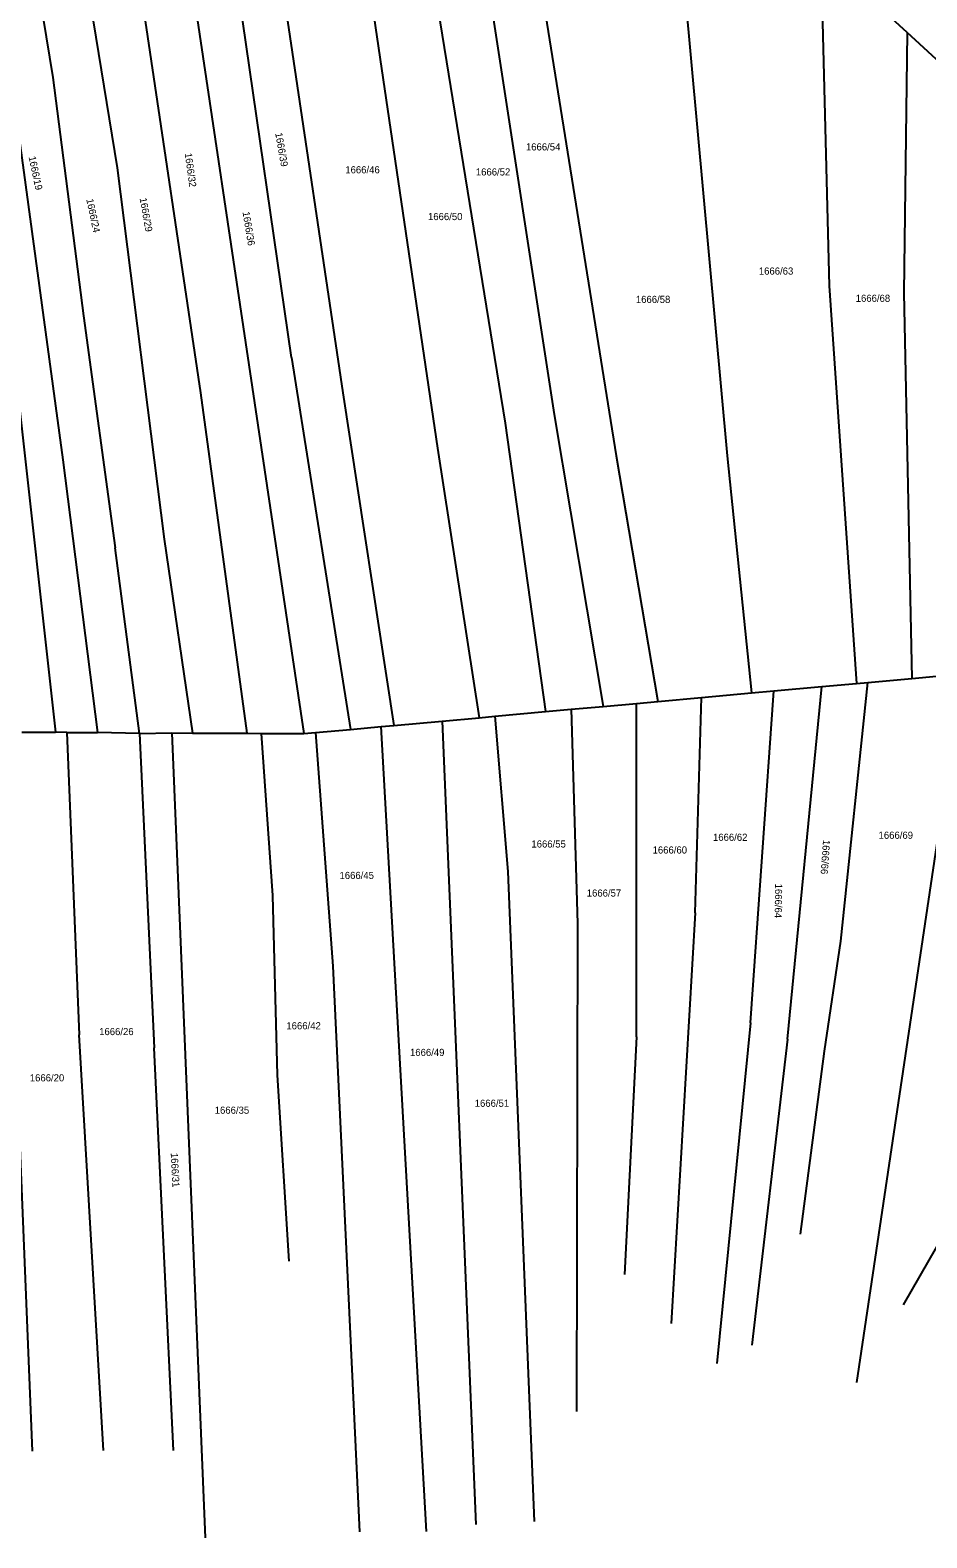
# Model space of a CAD drawing. Extents: x -563148 to -561712, y -1182311 to -1179502.
# Drawn here: x -562287.9 to -562099.2, y -1182310.8 to -1181993.6 of the extents above; entities that cross this region are included whole.
import ezdxf

# ---------------------------------------------------------------- set-up
doc = ezdxf.new("R2010")
doc.units = 0
doc.layers.add('Vrstva 55', color=7, linetype='Continuous')
doc.layers.add('Vrstva 57', color=7, linetype='Continuous')

msp = doc.modelspace()

# ---------------------------------------------------------------- linework, layer by layer
at = {"layer": 'Vrstva 55'}
for p, q in [((-562224.78, -1181928.78), (-562202.18, -1182081.56)), ((-562272.44, -1181932.73), (-562252.11, -1182069.88)), ((-562261.6, -1181931.83), (-562230.34, -1182141.58)), ((-562232.93, -1182062.44), (-562252, -1181931.04)), ((-562242.92, -1181930.28), (-562222.11, -1182069.88)), ((-562211.15, -1181933.38), (-562187.98, -1182076.29)), ((-562294.23, -1181936.71), (-562283.14, -1182003.55)), ((-562197.6, -1181944.66), (-562177.68, -1182074.46)), ((-562185.17, -1181955.01), (-562164.62, -1182083.16)), ((-562151.53, -1181970.25), (-562141.26, -1182083.16)), ((-562121.46, -1181982.4), (-562119.78, -1182047.41)), ((-562274.66, -1181991.63), (-562269.62, -1182022.56)), ((-562103.36, -1181994.11), (-562107.44, -1181990.36)), ((-562103.36, -1181994.11), (-562104.07, -1182048.88)), ((-562079.24, -1182016.32), (-562103.36, -1181994.11)), ((-562283.14, -1182003.55), (-562276.72, -1182053.72)), ((-562290.47, -1182014.77), (-562281.08, -1182083.96)), ((-562269.62, -1182022.56), (-562259.77, -1182100.69)), ((-562119.78, -1182047.41), (-562114.03, -1182131)), ((-562104.07, -1182048.88), (-562102.41, -1182129.95)), ((-562276.72, -1182053.72), (-562270.08, -1182102.52)), ((-562232.93, -1182062.44), (-562220.52, -1182140.69)), ((-562290.69, -1182068.61), (-562282.59, -1182141.29)), ((-562252.11, -1182069.88), (-562242.32, -1182141.51)), ((-562222.11, -1182069.88), (-562211.41, -1182139.86)), ((-562177.68, -1182074.46), (-562167.33, -1182135.85)), ((-562187.98, -1182076.29), (-562179.46, -1182136.95)), ((-562202.18, -1182081.56), (-562193.42, -1182138.22)), ((-562281.08, -1182083.96), (-562273.77, -1182141.34)), ((-562164.62, -1182083.16), (-562155.83, -1182134.8)), ((-562141.26, -1182083.16), (-562136.09, -1182133.01)), ((-562259.77, -1182100.69), (-562253.79, -1182141.45)), ((-562264.92, -1182141.53), (-562270.08, -1182102.52)), ((-562113.98, -1182278.04), (-562091.77, -1182128.98)), ((-562102.41, -1182129.95), (-562091.77, -1182128.98)), ((-562146.67, -1182133.97), (-562136.09, -1182133.01)), ((-562136.31, -1182202.4), (-562131.39, -1182132.58)), ((-562136.09, -1182133.01), (-562131.39, -1182132.58)), ((-562131.39, -1182132.58), (-562121.34, -1182131.67)), ((-562128.53, -1182205.84), (-562121.34, -1182131.67)), ((-562121.34, -1182131.67), (-562114.03, -1182131)), ((-562117.3, -1182185.22), (-562111.63, -1182130.79)), ((-562114.03, -1182131), (-562111.63, -1182130.79)), ((-562111.63, -1182130.79), (-562102.41, -1182129.95)), ((-562174.05, -1182136.46), (-562167.33, -1182135.85)), ((-562167.33, -1182135.85), (-562160.36, -1182135.22)), ((-562160.36, -1182135.22), (-562155.83, -1182134.8)), ((-562160.36, -1182205.38), (-562160.36, -1182135.22)), ((-562155.83, -1182134.8), (-562146.67, -1182133.97)), ((-562147.99, -1182179.26), (-562146.67, -1182133.97)), ((-562211.41, -1182139.86), (-562201.25, -1182138.94)), ((-562201.25, -1182138.94), (-562193.42, -1182138.22)), ((-562201.25, -1182138.94), (-562194.11, -1182307.92)), ((-562193.42, -1182138.22), (-562190.16, -1182137.93)), ((-562190.16, -1182137.93), (-562179.46, -1182136.95)), ((-562190.16, -1182137.93), (-562187.39, -1182170.56)), ((-562179.46, -1182136.95), (-562174.05, -1182136.46)), ((-562174.05, -1182136.46), (-562172.73, -1182181.55)), ((-562289.7, -1182141.25), (-562282.59, -1182141.29)), ((-562280.21, -1182141.31), (-562282.59, -1182141.29)), ((-562280.21, -1182141.31), (-562277.63, -1182204.92)), ((-562280.21, -1182141.31), (-562273.77, -1182141.34)), ((-562264.92, -1182141.53), (-562273.77, -1182141.34)), ((-562264.92, -1182141.53), (-562258.16, -1182141.42)), ((-562264.92, -1182141.53), (-562261.83, -1182207.67)), ((-562258.16, -1182141.42), (-562251.12, -1182310.75)), ((-562258.16, -1182141.42), (-562253.79, -1182141.45)), ((-562253.79, -1182141.45), (-562242.32, -1182141.51)), ((-562242.32, -1182141.51), (-562239.32, -1182141.53)), ((-562239.32, -1182141.53), (-562236.96, -1182175.64)), ((-562239.32, -1182141.53), (-562230.34, -1182141.58)), ((-562230.34, -1182141.58), (-562227.88, -1182141.36)), ((-562227.88, -1182141.36), (-562220.52, -1182140.69)), ((-562227.88, -1182141.36), (-562224.26, -1182190.49)), ((-562220.52, -1182140.69), (-562214.1, -1182140.1)), ((-562214.1, -1182140.1), (-562211.41, -1182139.86)), ((-562204.52, -1182309.43), (-562214.1, -1182140.1)), ((-562187.39, -1182170.56), (-562181.89, -1182307.33)), ((-562236.96, -1182175.64), (-562235.93, -1182213.41)), ((-562147.99, -1182179.26), (-562153.03, -1182265.64)), ((-562172.73, -1182181.55), (-562172.96, -1182284.19)), ((-562120.74, -1182208.36), (-562117.3, -1182185.22)), ((-562224.26, -1182190.49), (-562218.6, -1182309.52)), ((-562136.31, -1182202.4), (-562143.41, -1182274.11)), ((-562272.53, -1182292.37), (-562277.63, -1182204.92)), ((-562160.36, -1182205.38), (-562162.88, -1182255.33)), ((-562128.53, -1182205.84), (-562136.08, -1182270.22)), ((-562291.04, -1182206.2), (-562287.52, -1182292.5)), ((-562257.81, -1182292.37), (-562261.83, -1182207.67)), ((-562125.78, -1182246.85), (-562120.74, -1182208.36)), ((-562235.93, -1182213.41), (-562233.53, -1182252.57)), ((-562104.1, -1182261.73), (-562085.48, -1182229.17))]:
    msp.add_line(p, q, dxfattribs=at)

# ---------------------------------------------------------------- texts
at = {"layer": 'Vrstva 57'}
for s, rotation, p in [('1666/39', 279.9889, (-562236.38, -1182015.28)), ('1666/19', 281.9186, (-562288.28, -1182020.27)), ('1666/32', 277.8232, (-562255.41, -1182019.53)), ('1666/24', 281.9887, (-562276.14, -1182029.21)), ('1666/29', 280.0378, (-562264.91, -1182028.98)), ('1666/36', 279.4198, (-562243.25, -1182031.88)), ('1666/66', 265.9533, (-562121.06, -1182163.88)), ('1666/64', 269.3013, (-562131.16, -1182173.13)), ('1666/31', 273.0023, (-562258.36, -1182229.81))]:
    msp.add_text(s, height=1.5, rotation=rotation, dxfattribs=at).set_placement(p)
for s, p in [('1666/54', (-562183.6, -1182018.9)), ('1666/46', (-562221.62, -1182023.71)), ('1666/52', (-562194.14, -1182024.17)), ('1666/50', (-562204.21, -1182033.56)), ('1666/63', (-562134.58, -1182045.02)), ('1666/58', (-562160.46, -1182050.98)), ('1666/68', (-562114.19, -1182050.75)), ('1666/55', (-562182.45, -1182165.54)), ('1666/62', (-562144.23, -1182164.13)), ('1666/69', (-562109.38, -1182163.7)), ('1666/60', (-562156.94, -1182166.8)), ('1666/45', (-562222.84, -1182172.15)), ('1666/57', (-562170.8, -1182175.86)), ('1666/42', (-562234.02, -1182203.78)), ('1666/26', (-562273.42, -1182205)), ('1666/49', (-562208, -1182209.38)), ('1666/20', (-562288.02, -1182214.73)), ('1666/51', (-562194.38, -1182220.08)), ('1666/35', (-562249.1, -1182221.54))]:
    msp.add_text(s, height=1.5, dxfattribs=at).set_placement(p)

doc.saveas('drawing.dxf')
